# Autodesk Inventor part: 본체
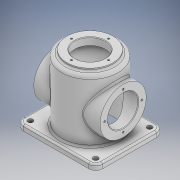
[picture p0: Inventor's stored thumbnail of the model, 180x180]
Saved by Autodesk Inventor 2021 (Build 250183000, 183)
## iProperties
Created: 2021-02
Part Number: 본체
Material: 일반
Document SubType Name: Modeling
Designer: 201-09
Density: 1 g/cm^3
Appearance: 기본값
Author: 201-09
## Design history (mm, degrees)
sketch "스케치1"
  geometry: L1 (-70, -60)-(70, -60); L2 (70, -60)-(70, 60); L3 (70, 60)-(-70, 60); L4 (-70, 60)-(-70, -60); L5 (-70, -60)-(70, 60); L6 (70, -60)-(-70, 60); C1 r 42 at (0, 0); 1 further point
  constraints: 12 end point, 2 midpoint, 2 parallel, 1 centre point, 1 coincident, 1 horizontal, 1 perpendicular
  dimensions: "d0" = 140 distance of L3.end L2.end; "d1" = 120 distance of L2.end L1.end; "d7" = 84 diameter of C1
extrude "돌출1" new body sketch "스케치1" distance "d2" = 10; taper "d3" = 0 deg
sketch "스케치2"
  geometry: C1 r 50 at (0, 0); 1 further point
  constraints: 1 centre point, 1 coincident
  dimensions: "d4" = 100 diameter of C1
extrude "돌출2" join sketch "스케치2" distance "d5" = 110; taper "d6" = 0 deg
extrude "돌출3" cut sketch "스케치1" distance "d8" = 112; taper "d9" = 0 deg
sketch "스케치3"
  geometry: C1 r 41 at (0, 0); 1 further point
  constraints: 1 centre point, 1 coincident
  dimensions: "d10" = 82 diameter of C1
extrude "돌출4" join sketch "스케치3" distance "d11" = 5; taper "d12" = 0 deg
sketch "스케치4"
  geometry: C1 r 27 at (0, 0); 1 further point
  constraints: 1 centre point, 1 coincident
  dimensions: "d13" = 54 diameter of C1
extrude "돌출5" cut sketch "스케치4" distance "d14" = 13; taper "d15" = 0 deg
node "작업 평면1"
node "작업 평면2"
sketch "스케치5"
  geometry: L1 (120, -50)-(120, 50) reference; L2 (10, 50)-(10, -50) reference; L3 (10, 50)-(10, -50) reference; L4 (10, -60)-(10, 60) reference; L5 (0, -60)-(0, 60) reference; C1 r 41 at (60, 0); C2 r 27 at (60, 0); A1 r 33 centre (60, 0) between (60, 33) and (93, 0); 5 further points
  constraints: 5 point on circle, 4 horizontal alignment, 3 centre point, 2 coincident, 2 vertical alignment, 1 midpoint
  dimensions: "d18" = 82 diameter of C1; "d19" = 60 distance from line of L5 C1.centre; "d20" = 54 diameter of C2; "d25" = 66 diameter of A1
  node "투영된 루프1"
extrude "돌출6" join sketch "스케치5" stored distance "d21" = 13; taper "d22" = 0 deg
extrude "돌출7" cut sketch "스케치5" stored distance "d23" = 13; taper "d24" = 0 deg
hole "구멍1" sketch "스케치5" diameter "d26" = 3.242; stored, may be unused: countersink angle "d30" = 90 deg, drill point angle "d32" = 118 deg; dims "d27" = 8, "d28" = 4, "d29" = 2, "d31" = 10
sketch "스케치6"
  geometry: C1 r 41 at (0, 0) reference; C2 r 27 at (0, 0) reference; A1 r 33 centre (0, 0) between (0, 33) and (33, 0); 3 further points
  constraints: 4 point on circle, 2 horizontal alignment, 2 vertical alignment, 1 centre point, 1 coincident
  dimensions: "d33" = 66 diameter of A1
hole "구멍2" sketch "스케치6" at (0, 33), (33, 0), (-33, 0), (0, -33) diameter "d34" = 3.242; stored, may be unused: countersink angle "d38" = 90 deg, drill point angle "d40" = 118 deg; dims "d35" = 8, "d36" = 4, "d37" = 2, "d39" = 10
sketch "스케치7"
  geometry: 1 further point
sketch "스케치8"
  geometry: L1 (-70, -60)-(-70, 60) reference; L2 (70, -60)-(-70, -60) reference; L3 (70, 60)-(70, -60) reference; L4 (-70, 60)-(70, 60) reference; C1 r 42 at (0, 0) reference; 1 further point
  node "투영된 루프2"
fillet "모깎기1" dims "d41" = 12
sketch "스케치9"
  geometry: L1 (70, 48)-(70, -48) reference; L2 (-58, 60)-(58, 60) reference; L3 (-70, -48)-(-70, 48) reference; L4 (58, -60)-(-58, -60) reference; C1 r 42 at (0, 0) reference; C2 r 4.5 at (58, 48); C3 r 4.5 at (58, -48); C4 r 4.5 at (-58, -48); C5 r 4.5 at (-58, 48); A1 r 12 centre (58, -48) between (58, -60) and (70, -48) reference; A2 r 12 centre (58, 48) between (70, 48) and (58, 60) reference; A3 r 12 centre (-58, 48) between (-58, 60) and (-70, 48) reference; A4 r 12 centre (-58, -48) between (-70, -48) and (-58, -60) reference; 1 further point
  constraints: 4 centre point, 4 coincident
  dimensions: "d42" = 9 diameter of C2; "d43" = 9 diameter of C3; "d44" = 9 diameter of C4; "d45" = 9 diameter of C5
extrude "돌출8" cut sketch "스케치9" extent not by distance; stored distance "d46" = 0; taper "d47" = 0 deg
fillet "모깎기2" dims "d48" = 3
fillet "모깎기3" dims "d49" = 3
fillet "모깎기4" dims "d50" = 6
fillet "모깎기5" dims "d51" = 3
fillet "모깎기6" dims "d52" = 3
chamfer "모따기1" distance "d53" = 1; stored, may be unused: second distance "d54" = 2, angle "d55" = 45 deg
chamfer "모따기2" distance "d56" = 1; stored, may be unused: second distance "d57" = 2, angle "d58" = 45 deg
chamfer "모따기3" distance "d59" = 1; stored, may be unused: second distance "d60" = 2, angle "d61" = 45 deg
fillet "모깎기7" dims "d62" = 3
node "작업 평면3"
sketch "스케치10"
  geometry: 2 further points
  constraints: 1 other
feature "엠보싱1" sketch "스케치10" dims "d0" = 140, "d1" = 120, "d64" = 0.5, "d65" = 0
node "솔리드1"
mirror "미러1"
node "투영된 루프3"
feature "A9D066F2-1C7D-4E18-AEED-F7BC21143FA4" dims "d26" = 3.242, "d27" = 8, "d28" = 4, "d29" = 2, "d30" = 90 deg, "d31" = 10, "d32" = 118 deg
other parameters: "d16" = -59, "d17" = 59, "d63" = -73.5
